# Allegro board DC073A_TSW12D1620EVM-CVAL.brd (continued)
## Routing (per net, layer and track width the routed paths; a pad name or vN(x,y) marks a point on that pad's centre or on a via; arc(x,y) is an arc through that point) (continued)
VBUS: length 10.1
  TOP w0.381: v1(13.92,39.23) 13.97,39.18 C167.1 13.97,38.27 v1(13.9,38.2)
  BOTTOM w0.381: U10.1 12,42.33 11.89,42.44 ; 11.89,42.44 12,42.54 12.58,42.54 13.9,41.22 U10.3 ; 11.89,42.44 R132.1
VBUSS: length 2.3
  TOP w0.381: FB3.1 11.9,35.31 v2(12,35.21)
VDDD33: length 2.7
  TOP w0.305: v1(24.42,32.2) 24.61,32.01 C170.1 24.61,31.4 24.44,31.22 v1(24.44,30.67)
  BOTTOM w0.152: U13.8 24.44,31.22 v1(24.44,30.67)
  vias: v1(5.97,115.82) v1(25.87,46.32) v1(25.93,43.44) v1(26.1,45.77) v1(26.14,42.89) v1(30.78,45.13) v1(30.78,44.12) v1(30.76,42.8) v1(52.25,35.94) v1(53.59,35.94) v1(57.89,35.94) v1(57.89,35.28) v1(57.91,31.39) v1(59.23,35.94) v1(59.23,35.28) v1(59.26,31.39) v2(16.59,59.97) v2(16.94,99.52) v2(16.97,107.52) v2(16.97,98.53) v2(17.45,78.03) v2(17.45,76.89) v2(17.42,75.72) v2(17.53,80.14) v2(17.48,79.1) v2(17.91,107.52) v2(17.88,99.49) v2(17.91,98.5) v2(18.11,59.94) v2(18.14,57.91) v2(18.14,56.39) v2(18.62,79.07) v2(18.59,78) v2(18.59,76.86) v2(18.57,75.69) v2(18.67,80.11) v2(19.74,78) v2(19.74,76.86) v2(19.71,75.69) v2(19.81,80.11) v2(19.76,79.07) v2(19.99,48.46) v2(29.08,34.92) v2(29.08,32.64) v2(29.08,31.5) v2(37.97,47.62) v2(37.97,45.09) v2(53.31,37.59) v2(65.05,117.27) v2(65.07,115.57) v2(65.81,116.41) v2(66.55,117.27) v2(66.52,115.57) v2(67.26,121.74) v2(67.26,110.62) v2(69.09,122.66) v2(69.09,121.72) v2(69.09,110.85) v2(69.09,109.93) v2(70.36,124.79) v2(71.63,124.79) v2(72.9,124.79) v2(74.17,124.79) v2(76.83,119.91) v2(76.81,119) v2(77.85,119.91) v2(77.85,119) v4(16.71,106.65) v4(17.25,106.65) v4(26.2,52.03) v4(26.2,51.22) v4(26.2,50.37) v4(28.7,40.84) v4(28.7,39.97) v4(28.7,39.15) v4(31.7,52.05) v4(31.7,51.22) v4(31.7,50.37) v4(33.24,44.85) v4(34.07,44.84) v4(34.85,44.84)
VDDL19: length 285.6
  L03_PWR w0.762: v2(64.85,38.05) 64.85,38.15
  L05_SIG1 w0.508: JP6.1 76.96,148.31 78.97,146.3 78.97,140.92 76.96,138.91 J12.1 ; JP6.1 JP7.1 JP8.1 JP9.1 ; JP6.1 JP5.1 JP4.1 JP3.1
  L08_SIG2 w0.762: v2(64.82,34.47) 63.88,34.47 54.13,24.71 29.13,24.71 19.86,33.99 19.86,46.99 20.75,47.88 20.75,62.38 20.35,62.79 20.35,71.96 21.72,73.33 21.72,93.67 17.73,97.66 12.67,97.66 10.01,100.33 10.01,111.63 9.27,112.37 9.27,125.4 12.73,128.85 12.73,130.51 15.98,133.76 15.98,134.19 18.59,136.8 18.59,137.82 23.83,143.05 31.29,143.05 32.74,144.5 38.25,144.5 42.01,148.26 63.04,148.26 JP9.1
  L10_SIG3 w0.508: v1(68.07,141.6) v1(72.52,141.6) 74.04,141.6 J12.1 ; JP3.1 92.3,146.84 92.3,140.82 v1(90.17,138.68)
  BOTTOM w0.762: J12.1 74.04,141.6 v1(72.52,141.6)
  vias: v1(52.25,35.28) v1(53.59,35.28) v2(54.61,32.77) v2(64.82,35.71) v2(64.87,36.86) v2(65.91,38.05) v2(65.94,36.86) v2(65.89,35.71) v2(65.89,34.47) v2(67.03,38.05) v2(67.01,35.71) v2(67.01,34.47) v2(67.06,36.86) v2(68.25,38.05) v2(68.22,35.71) v2(68.22,34.47) v2(68.28,36.86)
VEE: length 13.2
  TOP w0.305: JP10.3 81.41,116.59 81.84,116.59 87.27,111.15 R84.1 88.7,112.29 U6.8
VINI+: length 10.8
  TOP w0.178: 71.25,88.52 70.78,88.05 70.59,88.05 arc(70.39,88.09) 70.22,88.21 67.49,90.93 arc(67.33,91.17) 67.27,91.46 67.27,91.96 arc(67.21,92.29) 67.02,92.58 64.75,94.84 C2.2
VINI-: length 11
  TOP w0.178: C14.2 64.49,94.62 66.77,92.33 arc(66.89,92.16) 66.93,91.96 66.93,91.46 arc(67.01,91.04) 67.25,90.69 69.97,87.96 arc(70.26,87.77) 70.59,87.71 70.79,87.71 U4.J1
VINQ+: length 10.8
  TOP w0.178: R27.2 64.77,75.84 67.19,78.26 arc(67.38,78.54) 67.44,78.88 67.44,79.51 arc(67.48,79.72) 67.6,79.89 70.17,82.46 arc(70.34,82.57) 70.54,82.61 70.8,82.61 U4.N1
VINQ-: length 11
  TOP w0.178: U4.M1 70.76,82.96 70.54,82.96 arc(70.21,82.89) 69.92,82.7 67.36,80.13 arc(67.17,79.85) 67.1,79.51 67.1,78.88 arc(67.06,78.67) 66.94,78.5 64.51,76.07 R16.2
1P8V_USB: length 1.6
  BOTTOM w0.305: U12.49 32.2,39 32.6,38.6 v2(32.64,38.58)
  vias: v2(32.69,41.15) v2(33.07,39.67) v2(33.4,37.72) v2(33.43,36.73) v2(33.55,38.58) v4(21.98,47.35) v4(22.63,47.35) v4(24.69,40.78) v4(24.7,39.97) v4(24.69,39.12) v4(32.2,40.5) v4(32.2,39.77) v4(32.2,39.14) v4(33.22,47.35) v4(34.07,47.34) v4(34.89,47.35)
3P3USB: length 3.9
  TOP w0.305: v4(23.64,45.84) 24.53,45.84 FB2.2 24.71,47.32 PP6.1 ; v4(22.82,45.84) 21.98,45.84 v4(21.97,45.85)
3P3V_RX: length 1.7
  TOP w0.279: PP3.1 139.06,53.92 R115.2
3P3VAUX: length 65.9
  TOP w0.152: J30.4 94.36,33.71 95.66,35 101.83,35 102.16,35.33 102.16,38.77 v1(101.46,39.47) ; C155.2 v1(139.06,66.78)
  L10_SIG3 w0.127: v1(101.46,39.47) 101.45,39.48 101.45,41.53 110.64,50.72 113.67,50.72 119.74,56.79 124.64,56.79 126.95,54.48 128.04,54.48 129.08,55.52 129.08,56.2 139.06,66.18 v1(139.06,66.78)
12P0V_RX: length 3
  L10_SIG3 w0.127: v1(140.34,62.97) 139.8,62.43 139.8,60.96 v1(140.34,60.43)
/CS: length 89.8
  L10_SIG3 w0.127: v1(28.45,36.83) 18.67,36.83 13.13,42.37 13.13,65.3 12.29,66.14 12.29,70.69 9.68,73.3 9.68,90.27 16.84,97.43 17.75,97.43 18.75,98.42 18.75,104.42 v1(19.66,105.33)
  BOTTOM w0.152: U20.39 17.7,105.64 18.01,105.94 19.05,105.94 v1(19.66,105.33)
/RST: length 18.6
  BOTTOM w0.152: C238.1 SW2.2 R190.2 6.73,116.08 6.73,114.3 6.1,113.67 6.1,107.31 7.24,106.17 J36.11 7.33,106.14 U20.23
ADC_CLK: length 76.2
  TOP w0.152: PP7.1 v1(49.02,35.31)
  L05_SIG1 w0.076: v1(76.33,94.87) 76.33,94.82 75.72,94.21 75.72,93.37 75.34,92.99 70.74,92.99
  L05_SIG1 w0.127: v1(49.02,35.31) 49.02,36.86 66.42,54.25 66.42,65.65 66.29,65.77 66.29,66.78 66.03,67.05 66.03,67.42 66.29,67.68 66.29,75.16 66.41,75.28 66.41,76.14 66,76.54 66,85.38 66.41,85.79 66.41,89.45 69.95,92.99 70.74,92.99
ADC_SCSB: length 80.4
  TOP w0.152: PP8.1 v1(49.02,31.88)
  L05_SIG1 w0.076: v1(75.06,94.87) 75.06,94.72 74.55,94.21 70.74,94.21
  L05_SIG1 w0.127: v1(49.02,31.88) 49.66,32.51 49.66,34.29 49.17,34.77 48.74,34.77 48.36,35.15 48.36,37.19 65.58,54.41 65.58,65.82 65.19,66.21 65.19,66.58 65.58,66.97 65.58,73.56 65.1,74.04 65.1,77.93 64.58,78.45 64.58,81.32 65.1,81.83 65.1,86.39 65.79,87.08 65.79,90.12 69.88,94.21 70.74,94.21
ADC_SDI: length 78.7
  TOP w0.152: PP4.1 47.88,34.16 v1(49.02,34.16)
  L05_SIG1 w0.076: 70.74,95.45 74.37,95.45 v1(75.06,96.14)
  L05_SIG1 w0.127: 70.74,95.45 70.32,95.45 63.72,88.85 63.72,73.22 62.41,71.91 62.41,52.2 47.75,37.54 47.75,35.03 48.67,34.11 48.97,34.11 v1(49.02,34.16)
ADC_SDO: length 80.5
  TOP w0.152: v1(49.02,33.02) 47.75,33.02 PP5.1
  L05_SIG1 w0.076: v1(73.79,97.41) 73.18,96.8 70.74,96.8
  L05_SIG1 w0.127: v1(49.02,33.02) 46.66,35.38 46.66,38 61.84,53.17 61.84,65.69 61.84,65.69 61.84,76.14 61.91,76.22 61.91,76.59 61.84,76.66 61.84,83.26 61.94,83.36 61.94,83.72 61.84,83.82 61.84,87.81 61.84,87.81 61.84,88.16 70.48,96.8 70.74,96.8
AIN: length 1
  TOP w0.381: R3.1 C1.2
AINI: length 7.2
  TOP w0.381: J2.1 47.24,113.04 R5.1 C1.1
AINQ: length 7.2
  TOP w0.381: J5.1 47.42,57.84 47.44,57.84 C29.1
AIP: length 1
  TOP w0.381: R7.1 C6.2
AQN: length 1
  TOP w0.381: R18.1 48.16,60.17 C16.2
AQP: length 1
  TOP w0.381: C29.2 R25.1
BDBUS0: length 0.7
  TOP w0.254: R134.1 29.2,51.93 v4(29.2,51.22)
BDBUS1: length 3.2
  BOTTOM w0.254: v1(29.84,48.11) 29.7,48.25 U12.27
BDBUS2: length 5.8
  TOP w0.254: v1(30.2,49.62) 28.57,49.62 27.2,48.25 27.2,47.65 R136.1
  BOTTOM w0.254: U12.28 v1(30.2,49.62)
BDBUS3: length 3.2
  BOTTOM w0.254: U12.29 30.7,48.2 v1(30.79,48.11)
CALRUN: length 39.5
  L08_SIG2 w0.127: TP1.1 83.31,105.49 76.94,99.11 76.94,96.75 v1(76.33,96.14)
  BOTTOM w0.178: R40.1 77.01,99.42 77.01,96.82 v1(76.33,96.14)
CALRUN_FMC: length 63.9
  TOP w0.152: v1(135.25,84.56) 135.18,84.63 134.42,84.63 120.73,98.32 97.76,98.32 95.99,100.1 78.71,100.1 v1(78.05,99.44)
CALTRG: length 48.9
  L08_SIG2 w0.127: v1(77.6,93.6) 78.26,94.26 78.26,97.51 84.48,103.73 84.48,126.16 85.99,127.67 85.99,135.65 J9.2
  BOTTOM w0.152: R38.1 J9.2
CDBUS0: length 5.6
  BOTTOM w0.152: U12.38 35.44,46.84 35.76,47.17 35.76,49.23 R138.1
CDBUS1: length 4.8
  BOTTOM w0.152: R143.1 36.27,48.34 36.27,46.94 35.68,46.34 U12.39
CDBUS2: length 4.3
  BOTTOM w0.152: R142.2 R149.1 36.32,45.84 U12.40
CDBUS3: length 4.1
  BOTTOM w0.152: U12.41 36.7,45.34 R141.2 R150.1
CDBUS4: length 3.6
  BOTTOM w0.152: R151.1 35.16,44.34 U12.43
CLK+: length 4
  BOTTOM w0.381: C40.1 66.22,83.1 R53.2 65.5,84.75 T1.3
CLK-: length 4.1
  BOTTOM w0.381: T1.1 63.55,83.1 R53.1 65.52,82.36 65.52,82.29
CLKN: length 8.5
  BOTTOM w0.178: v1(71.25,75.82) 71.65,76.22 71.65,76.47 68.38,79.74 68.38,79.93 66.74,81.57 C42.2
CLKP: length 8.5
  BOTTOM w0.178: v1(72.52,77.09) 72.12,76.69 71.92,76.69 68.72,79.89 68.72,80.08 67.04,81.75 C41.2
CPOUT: length 6.9
  BOTTOM w0.178: U7.22 35.39,130.28 C132.1 38.05,131.47 C131.1 38.07,132.61 R90.1
DCLK_DI+: length 23.3
  TOP w0.178: v1(139.06,82.02) 139.06,81.84 138.79,81.56 134.5,81.56 132.18,83.87 131.4,83.87 128.58,86.68 118.45,86.68 C59.2
DCLK_DI-: length 23.3
  TOP w0.178: v1(139.06,80.75) 139.06,80.9 138.75,81.22 134.35,81.22 132.04,83.53 131.25,83.53 128.44,86.34 118.45,86.34 R194.2
DCLK_DID+: length 58.4
  TOP w0.178: v4(107.95,115.21) 108.16,115 108.72,115 112.2,111.52 112.2,110.73 110.34,108.86 110.34,108.36 110.71,107.98 111.22,107.98 113.08,109.85 113.87,109.85 114.45,109.27 114.45,108.49 112.58,106.62 112.58,106.12 112.96,105.74 113.46,105.74 115.33,107.61 116.12,107.61 116.7,107.03 116.7,106.24 114.83,104.37 114.83,103.87 115.2,103.49 115.71,103.49 117.58,105.36 118.36,105.36 118.94,104.78 118.94,103.99 117.07,102.13 117.07,101.62 117.45,101.25 117.95,101.25 119.82,103.11 120.61,103.11 124.39,99.33 135.08,99.33 135.25,99.51 v1(135.25,99.8)
DCLK_DID-: length 58.4
  TOP w0.178: v4(107.95,114.45) 108.16,114.66 108.58,114.66 111.86,111.38 111.86,110.87 109.99,109.01 109.99,108.22 110.57,107.64 111.36,107.64 113.23,109.51 113.73,109.51 114.11,109.13 114.11,108.63 112.24,106.76 112.24,105.97 112.82,105.4 113.6,105.4 115.47,107.26 115.97,107.26 116.35,106.89 116.35,106.38 114.48,104.51 114.48,103.73 115.06,103.15 115.85,103.15 117.72,105.02 118.22,105.02 118.6,104.64 118.6,104.14 116.73,102.27 116.73,101.48 117.31,100.9 118.1,100.9 119.96,102.77 120.47,102.77 124.25,98.99 135.08,98.99 135.25,98.81 v1(135.25,98.53)
DCLK_DQ+: length 23.3
  TOP w0.178: v1(131.44,75.67) 131.44,75.3 131.37,75.22 130.75,75.22 128.5,77.47 128.5,79.1 130.47,81.06 130.47,82.9 129.27,84.09 118.45,84.09 R197.1
DCLK_DQ-: length 23.4
  TOP w0.178: R196.1 118.45,83.75 129.13,83.75 130.12,82.75 130.12,81.21 128.16,79.24 128.16,77.33 130.61,74.88 131.37,74.88 131.44,74.8 v1(131.44,74.4)
DCLK_DQD+: length 57.3
  TOP w0.178: v4(108.71,117.25) 108.92,117.04 109.45,117.04 114.3,112.19 114.8,112.19 116.57,113.96 117.36,113.96 117.94,113.38 117.94,112.59 116.17,110.83 116.17,110.32 116.55,109.94 117.05,109.94 118.82,111.71 119.6,111.71 120.18,111.13 120.18,110.35 118.41,108.58 118.41,108.08 118.79,107.7 119.29,107.7 121.06,109.47 121.85,109.47 122.43,108.89 122.43,108.1 120.66,106.33 120.66,105.83 121.04,105.45 121.54,105.45 123.31,107.22 124.1,107.22 124.67,106.64 124.67,105.86 123,104.18 123,103.49 124.64,101.85 136.04,101.85 v1(136.53,102.34)
DCLK_DQD-: length 57.3
  TOP w0.178: v4(108.71,116.48) 108.92,116.69 109.31,116.69 114.16,111.85 114.95,111.85 116.71,113.62 117.22,113.62 117.59,113.24 117.59,112.74 115.83,110.97 115.83,110.18 116.4,109.6 117.19,109.6 118.96,111.37 119.46,111.37 119.84,110.99 119.84,110.49 118.07,108.72 118.07,107.94 118.65,107.36 119.44,107.36 121.21,109.12 121.71,109.12 122.09,108.75 122.09,108.24 120.32,106.48 120.32,105.69 120.9,105.11 121.68,105.11 123.45,106.88 123.95,106.88 124.33,106.5 124.33,106 122.66,104.32 122.66,103.35 124.5,101.51 136.11,101.51 136.53,101.09 v1(136.53,101.07)
DCLK_RST+: length 42.2
  L10_SIG3 w0.076: v1(39.5,81.53) 39.5,75.49 39.68,75.3 47.69,75.3 49.17,73.83 53.01,73.83 56.47,77.28 62.22,77.28 63.21,76.29 66.5,76.29 67.31,75.47 71.09,75.47 71.1,75.46 71.39,75.46 71.4,75.47 71.77,75.47 71.91,75.32 72.02,75.32 v1(72.52,75.82)
DCLK_RST-: length 42
  L10_SIG3 w0.076: v1(71.25,74.55) 71.74,75.04 71.74,75.15 71.67,75.23 71.5,75.23 71.49,75.22 71,75.22 70.99,75.23 67.21,75.23 66.4,76.05 63.11,76.05 62.12,77.04 56.57,77.04 53.11,73.58 49.07,73.58 47.59,75.06 39.71,75.06 39.5,74.85 v1(39.5,68.83)
DCLKI+: length 5.9
  L05_SIG1 w0.076: v1(94.11,85.98) 94.55,85.98 94.62,86.06 94.62,86.3 94.96,86.64 96.45,86.64 97.18,87.36 97.56,87.36 98.28,86.64 98.63,86.64 v4(98.88,86.89)
DCLKI-: length 5.9
  L05_SIG1 w0.076: v4(98.88,86.13) 98.62,86.4 98.18,86.4 97.46,87.12 97.28,87.12 96.44,86.29 96.44,86.18 96.36,86.11 96.14,86.11 96.06,86.18 96.06,86.29 95.95,86.4 95.06,86.4 94.86,86.2 94.86,86.06 94.94,85.98 v1(95.38,85.98)
DCLKIN: length 65.6
  TOP w0.178: R194.1 117.42,86.34 104.91,86.34 104.35,86.9 104.35,87.72 104.91,88.27 112.98,88.27 113.25,88.53 113.25,89.27 113,89.52 104.91,89.52 104.35,90.07 104.35,90.89 104.91,91.45 113.55,91.45 113.91,91.8 113.91,92.34 113.48,92.76 103.05,92.76 102.72,92.43 102.72,86.72 102.34,86.34 99.7,86.34 R65.1
DCLKIP: length 65.6
  TOP w0.178: R195.1 117.42,86.68 105.05,86.68 104.7,87.04 104.7,87.57 105.05,87.93 113.12,87.93 113.59,88.39 113.59,89.41 113.14,89.86 105.05,89.86 104.7,90.21 104.7,90.75 105.05,91.1 113.69,91.1 114.25,91.66 114.25,92.48 113.62,93.1 102.91,93.1 102.37,92.57 102.37,86.86 102.2,86.68 99.7,86.68 R64.1
DCLKQ+: length 5.9
  L05_SIG1 w0.076: v4(98.88,84.3) 98.62,84.04 97.52,84.04 96.15,85.41 94.94,85.41 94.62,85.09 94.62,84.79 94.55,84.71 v1(94.11,84.71)
DCLKQ-: length 5.9
  L05_SIG1 w0.076: v4(98.88,83.54) 98.62,83.8 97.42,83.8 96.64,84.58 96.48,84.58 96.42,84.51 96.23,84.51 96.15,84.6 96.15,84.78 96.21,84.85 96.21,85 96.05,85.17 95.04,85.17 94.86,84.99 94.86,84.79 94.94,84.71 v1(95.38,84.71)
DCLKQN: length 65.6
  TOP w0.178: R81.1 99.7,83.75 112.66,83.75 113.01,83.39 113.01,82.86 112.66,82.51 103.55,82.51 103.15,82.1 103.15,80.98 103.55,80.58 111.29,80.58 111.47,80.4 111.47,79.51 111.29,79.33 103.55,79.33 103,78.77 103,77.96 103.55,77.4 113.49,77.4 114.81,78.71 114.81,79.68 115.81,80.68 115.81,82.06 114.94,82.92 114.94,83.39 115.3,83.75 117.42,83.75 R196.2
DCLKQP: length 65.6
  TOP w0.178: R80.1 99.7,84.09 112.8,84.09 113.36,83.54 113.36,82.72 112.8,82.16 103.7,82.16 103.49,81.96 103.49,81.12 103.7,80.92 111.43,80.92 111.81,80.54 111.81,79.37 111.43,78.99 103.7,78.99 103.34,78.63 103.34,78.1 103.7,77.74 113.35,77.74 114.47,78.86 114.47,79.82 115.47,80.83 115.47,81.91 114.6,82.78 114.6,83.54 115.16,84.09 117.42,84.09 R197.2
DDRPH: length 85.6
  L08_SIG2 w0.127: v1(75.06,74.55) 74.4,75.21 71.09,75.21 68.5,77.8 68.5,81.28 69.09,81.86 69.09,90.25 68.52,90.82 68.52,91.19 69.02,91.7 69.02,102.22 75.15,108.34 75.15,118.99 72.36,121.77 72.36,125.45 71.02,126.8 68.88,126.8 67.69,127.99 67.69,132.89 65.3,135.28 65.3,144.63 JP9.2
DES: length 77.5
  L10_SIG3 w0.127: v1(76.33,75.82) 75.79,75.29 74.88,75.29 74.6,75.56 74.6,96.44 74.24,96.8 74.24,98.84 74.26,98.85 74.26,99.22 74.24,99.23 74.24,108.79 77.37,111.91 77.37,130.51 78.82,131.95 78.82,140 JP7.2
DEVCLKIN: length 24.3
  BOTTOM w0.381: v1(39.5,95.5) 48.06,95.5 56.62,86.94 59.71,86.94 T1.6
DI0+: length 81.3
  L05_SIG1 w0.076: v1(92.84,96.14) 92.34,95.64 92.34,95.53 92.42,95.46 92.58,95.46 92.59,95.47 93.05,95.47 93.37,95.78 93.37,96.49 93.83,96.95 94.2,96.95 94.64,97.39 94.64,97.69 95,98.04 100.16,98.04 107.55,90.65 107.78,90.65 107.99,90.86 108.16,90.86 108.37,90.65 108.76,90.65 109.16,91.05 109.16,91.76 109.45,92.05 110.19,92.05 110.48,91.76 110.48,89.41 110.63,89.26 111.17,89.26 111.32,89.41 111.32,91.76 111.61,92.05 112.35,92.05 112.64,91.76 112.64,89.41 112.79,89.26 113.33,89.26 113.48,89.41 113.48,91.76 113.77,92.05 114.51,92.05 114.8,91.76 114.8,89.41 114.95,89.26 115.48,89.26 115.64,89.41 115.64,91.76 115.93,92.05 116.66,92.05 116.96,91.76 116.96,89.41 117.11,89.26 117.54,89.26 117.8,89.51 117.8,91.76 118.09,92.05 118.52,92.05 119.91,90.65 120.7,90.65 129.86,81.5 135.61,81.5 136.04,81.06 136.04,80.64 136.52,80.16 138.13,80.16 138.65,79.65 138.65,79.3 138.99,78.96 140.26,78.96 140.34,79.04 v1(140.34,79.48)
DI0-: length 81.3
  L05_SIG1 w0.076: v1(91.57,94.87) 92.06,95.36 92.17,95.36 92.32,95.22 92.68,95.22 92.69,95.22 93.15,95.22 93.61,95.68 93.61,96.39 93.93,96.71 94.3,96.71 94.88,97.29 94.88,97.59 95.1,97.8 100.06,97.8 107.45,90.41 108.86,90.41 109.4,90.95 109.4,91.66 109.55,91.81 110.09,91.81 110.24,91.66 110.24,89.31 110.53,89.01 111.27,89.01 111.56,89.31 111.56,91.66 111.71,91.81 112.25,91.81 112.4,91.66 112.4,89.31 112.69,89.01 113.43,89.01 113.72,89.31 113.72,91.66 113.87,91.81 114.41,91.81 114.56,91.66 114.56,89.31 114.85,89.01 115.58,89.01 115.88,89.31 115.88,91.66 116.03,91.81 116.56,91.81 116.72,91.66 116.72,89.31 117.01,89.01 117.64,89.01 118.04,89.41 118.04,91.66 118.19,91.81 118.42,91.81 119.81,90.41 120.6,90.41 129.76,81.25 135.51,81.25 135.8,80.96 135.8,80.54 136.42,79.92 138.03,79.92 138.4,79.55 138.4,79.2 138.89,78.72 140.26,78.72 140.34,78.64 v1(140.34,78.21)
DI1+: length 81.2
  L05_SIG1 w0.076: v1(94.11,96.14) 94.51,96.14 94.61,96.25 94.61,96.47 95.08,96.94 99.23,96.94 106.78,89.38 106.78,81.2 106.32,80.75 106.32,80.29 106.6,80.01 107.88,80.01 108.08,80.21 108.08,84.18 108.41,84.51 109.11,84.51 109.4,84.21 109.4,80.21 109.55,80.06 110.09,80.06 110.24,80.21 110.24,84.21 110.53,84.51 111.26,84.51 111.56,84.21 111.56,80.21 111.71,80.06 112.21,80.06 112.36,80.21 112.36,84.17 112.69,84.51 113.42,84.51 113.72,84.21 113.72,80.22 113.88,80.06 114.22,80.06 116.47,82.31 126.64,82.31 128.89,80.06 132.64,80.06 133.74,78.96 133.91,78.96 133.99,79.04 v1(133.99,79.48)
DI1-: length 81.3
  L05_SIG1 w0.076: v1(95.38,96.14) 94.98,96.14 94.85,96.26 94.85,96.37 95.18,96.7 96.03,96.7 96.23,96.49 96.41,96.49 96.61,96.7 99.13,96.7 99.43,96.39 99.43,96.17 99.59,96.01 99.81,96.01 106.54,89.28 106.54,88.89 106.32,88.68 106.32,88.51 106.54,88.3 106.54,81.3 106.08,80.85 106.08,80.19 106.5,79.77 107.98,79.77 108.32,80.11 108.32,84.08 108.51,84.26 109.01,84.26 109.16,84.11 109.16,80.11 109.45,79.82 110.19,79.82 110.48,80.11 110.48,84.11 110.63,84.26 111.16,84.26 111.32,84.11 111.32,80.11 111.61,79.82 112.31,79.82 112.6,80.11 112.6,84.07 112.79,84.26 113.32,84.26 113.48,84.11 113.48,80.12 113.78,79.82 114.32,79.82 116.57,82.07 126.54,82.07 128.79,79.82 132.54,79.82 133.64,78.72 133.91,78.72 133.99,78.64 v1(133.99,78.21)
DI2+: length 81.4
  L05_SIG1 w0.076: v1(94.11,94.87) 94.51,94.87 94.61,94.97 94.61,95.22 94.95,95.57 98.88,95.57 105.44,89.01 105.44,81 104.19,79.76 104.19,79.15 104.53,78.8 125.49,78.8 125.59,78.91 125.59,79.44 125.38,79.65 116.94,79.65 116.71,79.88 116.71,80.62 117.01,80.91 126.23,80.91 126.91,80.22 126.91,78.37 127.33,77.95 128.49,77.95 129.53,78.99 132.52,78.99 133.75,77.76 134.3,77.76 134.57,78.03 134.57,80.01 134.79,80.23 135.18,80.23 135.25,80.31 v1(135.25,80.75)
DI2-: length 81.4
  L05_SIG1 w0.076: v1(95.38,94.87) 94.98,94.87 94.88,94.97 94.88,95.11 95.09,95.33 95.9,95.33 96.1,95.12 96.28,95.12 96.48,95.33 98.78,95.33 99.03,95.07 99.03,94.77 99.15,94.65 99.46,94.65 105.19,88.91 105.19,88.61 105.03,88.44 105.03,88.23 105.19,88.06 105.19,81.1 103.95,79.86 103.95,79.05 104.43,78.56 125.59,78.56 125.83,78.81 125.83,79.54 125.48,79.9 117.04,79.9 116.95,79.98 116.95,80.52 117.11,80.67 126.13,80.67 126.67,80.12 126.67,78.27 127.23,77.71 128.59,77.71 129.63,78.75 132.42,78.75 133.65,77.52 134.4,77.52 134.81,77.93 134.81,79.91 134.89,79.99 135.18,79.99 135.25,79.91 v1(135.25,79.48)
DI3+: length 81.3
  L05_SIG1 w0.076: v1(92.84,93.6) 92.84,93.24 93.03,93.05 97.97,93.05 102.55,88.47 102.55,81.51 101.52,80.48 101.52,78.38 99.59,76.45 99.59,74.9 100.18,74.32 101.74,74.32 101.89,74.47 101.89,75.02 102.19,75.31 102.92,75.31 103.21,75.02 103.21,74.47 103.37,74.32 103.9,74.32 104.05,74.47 104.05,75.02 104.35,75.31 105.08,75.31 105.37,75.02 105.37,74.47 105.53,74.32 106.06,74.32 106.21,74.47 106.21,75.02 106.5,75.31 107.24,75.31 107.53,75.02 107.53,74.47 107.68,74.32 108.22,74.32 108.37,74.47 108.37,75.02 108.66,75.31 109.4,75.31 109.69,75.02 109.69,74.47 109.84,74.32 110.38,74.32 110.53,74.47 110.53,75.02 110.82,75.31 111.56,75.31 111.85,75.02 111.85,74.47 112,74.32 112.54,74.32 112.69,74.47 112.69,75.02 112.98,75.31 113.72,75.31 114.01,75.02 114.01,74.47 114.16,74.32 114.69,74.32 114.85,74.47 114.85,75.02 115.14,75.31 115.87,75.31 116.17,75.02 116.17,74.47 116.32,74.32 116.85,74.32 117.01,74.47 117.01,75.02 117.3,75.31 118.03,75.31 118.33,75.02 118.33,74.47 118.48,74.32 119.01,74.32 119.17,74.47 119.17,75.02 119.46,75.31 120.19,75.31 120.49,75.02 120.49,74.47 120.64,74.32 121.17,74.32 121.32,74.47 121.32,75.02 121.62,75.31 122.35,75.31 122.65,75.02 122.65,74.47 122.8,74.32 123.33,74.32 123.48,74.47 123.48,75.02 123.78,75.31 124.51,75.31 124.8,75.02 124.8,74.47 124.96,74.32 125.49,74.32 125.64,74.47 125.64,75.02 125.94,75.31 126.67,75.31 126.96,75.02 126.96,74.47 127.34,74.09 128.14,74.09 130.47,76.42 132.9,76.42 133.44,75.88 133.44,75.49 133.77,75.15 133.91,75.15 133.99,75.23 v1(133.99,75.67)
DI3-: length 81.2
  L05_SIG1 w0.076: v1(92.84,92.33) 92.84,92.62 93.03,92.81 97.87,92.81 102.31,88.37 102.31,81.61 101.28,80.58 101.28,78.48 99.35,76.55 99.35,74.8 100.08,74.08 101.84,74.08 102.13,74.37 102.13,74.92 102.29,75.07 102.82,75.07 102.97,74.92 102.97,74.37 103.27,74.08 104,74.08 104.29,74.37 104.29,74.92 104.45,75.07 104.98,75.07 105.13,74.92 105.13,74.37 105.43,74.08 106.16,74.08 106.45,74.37 106.45,74.92 106.61,75.07 107.14,75.07 107.29,74.92 107.29,74.37 107.58,74.08 108.32,74.08 108.61,74.37 108.61,74.92 108.76,75.07 109.3,75.07 109.45,74.92 109.45,74.37 109.74,74.08 110.48,74.08 110.77,74.37 110.77,74.92 110.92,75.07 111.46,75.07 111.61,74.92 111.61,74.37 111.9,74.08 112.64,74.08 112.93,74.37 112.93,74.92 113.08,75.07 113.62,75.07 113.77,74.92 113.77,74.37 114.06,74.08 114.8,74.08 115.09,74.37 115.09,74.92 115.24,75.07 115.77,75.07 115.93,74.92 115.93,74.37 116.22,74.08 116.95,74.08 117.25,74.37 117.25,74.92 117.4,75.07 117.93,75.07 118.09,74.92 118.09,74.37 118.38,74.08 119.11,74.08 119.41,74.37 119.41,74.92 119.56,75.07 120.09,75.07 120.24,74.92 120.24,74.37 120.54,74.08 121.27,74.08 121.57,74.37 121.57,74.92 121.72,75.07 122.25,75.07 122.4,74.92 122.4,74.37 122.7,74.08 123.43,74.08 123.72,74.37 123.72,74.92 123.88,75.07 124.41,75.07 124.56,74.92 124.56,74.37 124.86,74.08 125.59,74.08 125.88,74.37 125.88,74.92 126.04,75.07 126.57,75.07 126.72,74.92 126.72,74.37 127.24,73.85 128.24,73.85 130.57,76.17 132.8,76.17 133.2,75.78 133.2,75.39 133.67,74.91 133.91,74.91 133.99,74.83 v1(133.99,74.4)
DI4+: length 81.3
  L05_SIG1 w0.076: v1(94.11,93.6) 94.51,93.6 94.61,93.7 94.61,94 94.93,94.32 98.4,94.32 103.99,88.73 103.99,81.05 102.57,79.63 102.57,77.85 101.42,76.71 101.42,76.45 101.57,76.3 103.86,76.3 104.01,76.45 104.01,77.15 104.38,77.52 104.96,77.52 105.33,77.15 105.33,76.45 105.48,76.3 106.01,76.3 106.17,76.45 106.17,77.15 106.46,77.44 107.19,77.44 107.49,77.15 107.49,76.45 107.64,76.3 108.17,76.3 108.33,76.45 108.33,77.15 108.62,77.44 109.35,77.44 109.65,77.15 109.65,76.45 109.8,76.3 110.33,76.3 110.49,76.45 110.49,77.15 110.78,77.44 111.51,77.44 111.81,77.15 111.81,76.45 111.96,76.3 112.49,76.3 112.64,76.45 112.64,77.15 112.94,77.44 113.67,77.44 113.96,77.15 113.96,76.45 114.12,76.3 114.65,76.3 114.8,76.45 114.8,77.15 115.1,77.44 115.83,77.44 116.12,77.15 116.12,76.45 116.28,76.3 116.81,76.3 117.01,76.5 117.01,77.19 117.26,77.44 117.99,77.44 118.33,77.11 118.33,76.41 118.44,76.3 118.97,76.3 119.12,76.45 119.12,77.15 119.41,77.44 120.15,77.44 120.44,77.15 120.44,76.45 120.59,76.3 121.13,76.3 121.28,76.45 121.28,77.15 121.57,77.44 122.31,77.44 122.6,77.15 122.6,76.45 122.75,76.3 123.29,76.3 123.44,76.45 123.44,77.15 123.73,77.44 124.47,77.44 124.76,77.15 124.76,76.45 124.91,76.3 125.45,76.3 125.6,76.45 125.6,77.15 125.89,77.44 126.63,77.44 126.92,77.15 126.92,76.45 127.4,75.97 128.26,75.97 129.92,77.64 132.95,77.64 133.38,77.21 133.38,76.9 133.84,76.43 135.18,76.43 135.25,76.5 v1(135.25,76.94)
DI4-: length 81.3
  L05_SIG1 w0.076: v1(135.25,75.67) 135.25,76.11 135.18,76.19 133.74,76.19 133.13,76.8 133.13,77.11 132.85,77.39 130.02,77.39 128.36,75.73 127.3,75.73 126.68,76.35 126.68,77.05 126.53,77.2 125.99,77.2 125.84,77.05 125.84,76.35 125.55,76.06 124.81,76.06 124.52,76.35 124.52,77.05 124.37,77.2 123.83,77.2 123.68,77.05 123.68,76.35 123.39,76.06 122.65,76.06 122.36,76.35 122.36,77.05 122.21,77.2 121.67,77.2 121.52,77.05 121.52,76.35 121.23,76.06 120.49,76.06 120.2,76.35 120.2,77.05 120.05,77.2 119.51,77.2 119.36,77.05 119.36,76.35 119.07,76.06 118.34,76.06 118.08,76.31 118.08,77.01 117.89,77.2 117.36,77.2 117.25,77.09 117.25,76.4 116.91,76.06 116.18,76.06 115.88,76.35 115.88,77.05 115.73,77.2 115.2,77.2 115.04,77.05 115.04,76.35 114.75,76.06 114.02,76.06 113.72,76.35 113.72,77.05 113.57,77.2 113.04,77.2 112.89,77.05 112.89,76.35 112.59,76.06 111.86,76.06 111.56,76.35 111.56,77.05 111.41,77.2 110.88,77.2 110.73,77.05 110.73,76.35 110.43,76.06 109.7,76.06 109.41,76.35 109.41,77.05 109.25,77.2 108.72,77.2 108.57,77.05 108.57,76.35 108.27,76.06 107.54,76.06 107.25,76.35 107.25,77.05 107.09,77.2 106.56,77.2 106.41,77.05 106.41,76.35 106.11,76.06 105.38,76.06 105.09,76.35 105.09,77.05 104.86,77.28 104.48,77.28 104.25,77.05 104.25,76.35 103.96,76.06 101.47,76.06 101.18,76.35 101.18,76.81 102.32,77.95 102.32,79.73 103.75,81.15 103.75,87.64 103.61,87.78 103.61,88.09 103.75,88.23 103.75,88.63 98.94,93.44 98.68,93.44 98.54,93.58 98.54,93.84 98.3,94.08 96.57,94.08 96.39,93.9 96.19,93.9 96.01,94.08 95.07,94.08 94.88,93.89 94.88,93.7 94.98,93.6 v1(95.38,93.6)
DI5+: length 81.1
  L08_SIG2 w0.076: v1(94.11,92.33) 94.51,92.33 94.61,92.23 94.61,92.03 95.21,91.43 96.23,91.43 99.35,88.3 99.35,84.41 99.98,83.78 100.28,83.78 101.05,83.78 101.34,84.08 101.34,85.43 101.5,85.59 102.03,85.59 102.18,85.43 102.18,84.08 102.48,83.78 103.21,83.78 103.5,84.08 103.5,85.43 103.65,85.59 104.19,85.59 104.34,85.43 104.34,84.08 104.63,83.78 105.37,83.78 105.66,84.08 105.66,85.43 105.81,85.59 106.35,85.59 106.5,85.43 106.5,84.08 106.79,83.78 107.53,83.78 107.82,84.08 107.82,85.43 107.97,85.59 108.51,85.59 108.66,85.43 108.66,84.08 108.95,83.78 109.69,83.78 109.98,84.08 109.98,85.46 110.11,85.59 110.67,85.59 110.82,85.43 110.82,84.08 111.11,83.78 111.84,83.78 112.14,84.08 112.14,85.43 112.29,85.59 112.7,85.59 112.98,85.31 112.98,84.08 113.27,83.78 113.97,83.78 114.31,84.13 114.31,85.51 114.39,85.59 114.98,85.59 115.14,85.43 115.14,84.08 115.43,83.78 138.28,83.78 140.04,82.02 140.04,81.76 140.24,81.55 140.51,81.55 140.89,81.17 140.89,79.12 140.77,78.99 140.77,78.61 140.89,78.49 140.89,78.01 140.58,77.7 139.24,77.7 139.06,77.88 v1(139.06,78.21)
DI5-: length 81.3
  L08_SIG2 w0.076: v1(139.06,76.94) 139.06,77.28 139.24,77.46 140.68,77.46 141.14,77.91 141.14,81.27 138.38,84.02 115.53,84.02 115.38,84.18 115.38,85.53 115.08,85.83 114.29,85.83 114.07,85.61 114.07,84.23 113.87,84.02 113.37,84.02 113.22,84.18 113.22,85.41 112.8,85.83 112.19,85.83 111.9,85.53 111.9,84.18 111.74,84.02 111.21,84.02 111.06,84.18 111.06,85.53 110.77,85.83 110.01,85.83 109.74,85.56 109.74,84.18 109.59,84.02 109.05,84.02 108.9,84.18 108.9,85.53 108.61,85.83 107.87,85.83 107.58,85.53 107.58,84.18 107.43,84.02 106.89,84.02 106.74,84.18 106.74,85.53 106.45,85.83 105.71,85.83 105.42,85.53 105.42,84.18 105.27,84.02 104.73,84.02 104.58,84.18 104.58,85.53 104.29,85.83 103.55,85.83 103.26,85.53 103.26,84.18 103.11,84.02 102.58,84.02 102.42,84.18 102.42,85.53 102.13,85.83 101.4,85.83 101.1,85.53 101.1,84.18 100.95,84.02 100.18,84.02 100.18,84.02 100.08,84.02 99.59,84.51 99.59,88.4 96.33,91.67 95.31,91.67 94.88,92.11 94.88,92.23 94.98,92.33 v1(95.38,92.33)
DI6+: length 81.3
  L08_SIG2 w0.076: v1(92.84,91.06) 93.28,91.06 93.35,91.14 93.35,91.39 93.73,91.77 94.36,91.77 94.82,91.31 94.82,91.02 95.27,90.56 95.68,90.56 96.56,89.69 96.56,88.44 95.81,87.69 93.9,87.69 93.6,87.39 93.6,73.01 94.54,72.07 97.49,72.07 98.92,73.51 99.62,73.51 99.91,73.21 99.91,72.85 100.07,72.69 100.6,72.69 100.75,72.85 100.75,73.21 101.05,73.51 101.78,73.51 102.07,73.21 102.07,72.85 102.23,72.69 102.76,72.69 102.91,72.85 102.91,73.21 103.2,73.51 103.94,73.51 104.23,73.21 104.23,72.85 104.38,72.69 104.92,72.69 105.07,72.85 105.07,73.21 105.36,73.51 106.1,73.51 106.39,73.21 106.39,72.85 106.54,72.69 107.08,72.69 107.23,72.85 107.23,73.21 107.52,73.51 108.26,73.51 108.55,73.21 108.55,72.85 108.7,72.69 109.24,72.69 109.39,72.85 109.39,73.21 109.68,73.51 110.42,73.51 110.71,73.21 110.71,72.85 110.86,72.69 111.39,72.69 111.55,72.85 111.55,73.21 111.84,73.51 112.57,73.51 112.87,73.21 112.87,72.85 113.02,72.69 113.55,72.69 113.71,72.85 113.71,73.21 114,73.51 114.73,73.51 115.03,73.21 115.03,72.85 115.18,72.69 115.71,72.69 115.86,72.85 115.86,73.21 116.16,73.51 116.89,73.51 117.19,73.21 117.19,72.85 117.34,72.69 117.87,72.69 118.02,72.85 118.02,73.21 118.32,73.51 119.05,73.51 119.34,73.21 119.34,72.85 119.5,72.69 120.03,72.69 120.18,72.85 120.18,73.21 120.48,73.51 121.21,73.51 121.5,73.21 121.5,72.85 121.66,72.69 122.19,72.69 122.34,72.85 122.34,73.21 122.64,73.51 123.37,73.51 123.66,73.21 123.66,72.85 123.82,72.69 124.35,72.69 124.5,72.85 124.5,73.21 124.79,73.51 125.53,73.51 125.82,73.21 125.82,72.85 125.97,72.69 126.51,72.69 126.66,72.85 126.66,73.21 126.95,73.51 127.69,73.51 128.5,72.69 129.78,72.69 131.14,71.34 133.87,71.34 133.89,71.32 133.99,71.42 v1(133.99,71.86)
DI6-: length 81.2
  L08_SIG2 w0.076: v1(94.11,91.06) 93.67,91.06 93.59,91.14 93.59,91.29 93.83,91.53 94.26,91.53 94.58,91.21 94.58,90.92 94.74,90.76 94.74,90.6 94.68,90.54 94.68,90.38 94.79,90.27 94.95,90.27 95.01,90.33 95.17,90.33 95.17,90.32 95.58,90.32 96.32,89.59 96.32,88.54 95.71,87.93 93.8,87.93 93.36,87.49 93.36,72.91 94.44,71.83 97.59,71.83 99.02,73.27 99.52,73.27 99.67,73.11 99.67,72.75 99.97,72.45 100.7,72.45 100.99,72.75 100.99,73.11 101.15,73.27 101.68,73.27 101.83,73.11 101.83,72.75 102.13,72.45 102.86,72.45 103.15,72.75 103.15,73.11 103.3,73.27 103.84,73.27 103.99,73.11 103.99,72.75 104.28,72.45 105.02,72.45 105.31,72.75 105.31,73.11 105.46,73.27 106,73.27 106.15,73.11 106.15,72.75 106.44,72.45 107.18,72.45 107.47,72.75 107.47,73.11 107.62,73.27 108.16,73.27 108.31,73.11 108.31,72.75 108.6,72.45 109.34,72.45 109.63,72.75 109.63,73.11 109.78,73.27 110.31,73.27 110.47,73.11 110.47,72.75 110.76,72.45 111.49,72.45 111.79,72.75 111.79,73.11 111.94,73.27 112.47,73.27 112.63,73.11 112.63,72.75 112.92,72.45 113.65,72.45 113.95,72.75 113.95,73.11 114.1,73.27 114.63,73.27 114.79,73.11 114.79,72.75 115.08,72.45 115.81,72.45 116.11,72.75 116.11,73.11 116.26,73.27 116.79,73.27 116.94,73.11 116.94,72.75 117.24,72.45 117.97,72.45 118.27,72.75 118.27,73.11 118.42,73.27 118.95,73.27 119.1,73.11 119.1,72.75 119.4,72.45 120.13,72.45 120.42,72.75 120.42,73.11 120.58,73.27 121.11,73.27 121.26,73.11 121.26,72.75 121.56,72.45 122.29,72.45 122.58,72.75 122.58,73.11 122.74,73.27 123.27,73.27 123.42,73.11 123.42,72.75 123.72,72.45 124.45,72.45 124.74,72.75 124.74,73.11 124.89,73.27 125.43,73.27 125.58,73.11 125.58,72.75 125.87,72.45 126.61,72.45 126.9,72.75 126.9,73.11 127.05,73.27 127.59,73.27 128.4,72.45 129.68,72.45 131.04,71.09 133.77,71.09 133.99,70.88 v1(133.99,70.59)
DI7+: length 81.3
  L05_SIG1 w0.076: v1(91.57,89.79) 92.01,89.79 92.08,89.87 92.08,90.35 92.3,90.56 98.6,90.56 101.21,87.96 101.21,82.13 100.28,81.2 100.28,78.69 98.55,76.96 98.55,72.63 98.94,72.24 99.59,72.24 99.97,72.61 99.97,73.16 100.26,73.46 101,73.46 101.29,73.16 101.29,72.82 101.44,72.67 101.98,72.67 102.13,72.82 102.13,73.16 102.42,73.46 103.16,73.46 103.45,73.16 103.45,72.82 103.6,72.67 104.14,72.67 104.29,72.82 104.29,73.16 104.58,73.46 105.32,73.46 105.61,73.16 105.61,72.82 105.76,72.67 106.29,72.67 106.45,72.82 106.45,73.16 106.74,73.46 107.47,73.46 107.77,73.16 107.77,72.82 107.92,72.67 108.45,72.67 108.61,72.82 108.61,73.16 108.9,73.46 109.63,73.46 109.93,73.16 109.93,72.76 110,72.68 110.63,72.68 110.77,72.82 110.77,73.16 111.06,73.46 111.79,73.46 112.09,73.16 112.09,72.82 112.24,72.67 112.77,72.67 112.92,72.82 112.92,73.16 113.22,73.46 113.95,73.46 114.25,73.16 114.25,72.82 114.4,72.67 114.93,72.67 115.08,72.82 115.08,73.16 115.38,73.46 116.11,73.46 116.4,73.16 116.4,72.82 116.56,72.67 117.09,72.67 117.24,72.82 117.24,73.16 117.54,73.46 118.27,73.46 118.56,73.16 118.56,72.82 118.72,72.67 119.25,72.67 119.4,72.82 119.4,73.16 119.69,73.46 120.43,73.46 120.72,73.16 120.72,72.82 120.87,72.67 121.41,72.67 121.56,72.82 121.56,73.16 121.85,73.46 122.59,73.46 122.88,73.16 122.88,72.82 123.03,72.67 123.57,72.67 123.72,72.82 123.72,73.16 124.01,73.46 124.75,73.46 125.04,73.16 125.04,72.82 125.95,71.91 127.46,71.91 130.75,75.2 132.85,75.2 133.38,74.67 133.38,74.41 133.91,73.88 134.36,73.88 134.81,73.43 134.81,72.82 135.02,72.61 135.18,72.61 135.25,72.69 v1(135.25,73.13)
DI7-: length 81.3
  L05_SIG1 w0.076: v1(135.25,71.86) 135.25,72.29 135.18,72.37 134.92,72.37 134.57,72.72 134.57,73.33 134.26,73.63 133.81,73.63 133.13,74.31 133.13,74.57 132.75,74.96 130.85,74.96 127.56,71.67 125.85,71.67 124.8,72.72 124.8,73.06 124.65,73.22 124.11,73.22 123.96,73.06 123.96,72.72 123.67,72.43 122.93,72.43 122.64,72.72 122.64,73.06 122.49,73.22 121.95,73.22 121.8,73.06 121.8,72.72 121.51,72.43 120.77,72.43 120.48,72.72 120.48,73.06 120.33,73.22 119.8,73.22 119.64,73.06 119.64,72.72 119.35,72.43 118.62,72.43 118.32,72.72 118.32,73.06 118.17,73.22 117.64,73.22 117.48,73.06 117.48,72.72 117.19,72.43 116.46,72.43 116.16,72.72 116.16,73.06 116.01,73.22 115.48,73.22 115.32,73.06 115.32,72.72 115.03,72.43 114.3,72.43 114,72.72 114,73.06 113.85,73.22 113.32,73.22 113.17,73.06 113.17,72.72 112.87,72.43 112.14,72.43 111.84,72.72 111.84,73.06 111.69,73.22 111.16,73.22 111.01,73.06 111.01,72.72 110.73,72.44 109.9,72.44 109.69,72.66 109.69,73.06 109.53,73.22 109,73.22 108.85,73.06 108.85,72.72 108.55,72.43 107.82,72.43 107.53,72.72 107.53,73.06 107.37,73.22 106.84,73.22 106.69,73.06 106.69,72.72 106.4,72.43 105.66,72.43 105.37,72.72 105.37,73.06 105.22,73.22 104.68,73.22 104.53,73.06 104.53,72.72 104.24,72.43 103.5,72.43 103.21,72.72 103.21,73.06 103.06,73.22 102.52,73.22 102.37,73.06 102.37,72.72 102.08,72.43 101.34,72.43 101.05,72.72 101.05,73.06 100.9,73.22 100.36,73.22 100.21,73.06 100.21,72.51 99.69,72 98.84,72 98.31,72.53 98.31,77.06 100.04,78.79 100.04,81.3 100.97,82.23 100.97,86.98 100.81,87.14 100.81,87.36 100.97,87.52 100.97,87.86 99.19,89.63 98.96,89.63 98.81,89.79 98.81,90.01 98.5,90.32 96.64,90.32 96.47,90.14 96.26,90.14 96.08,90.32 92.4,90.32 92.32,90.25 92.32,89.87 92.4,89.79 v1(92.84,89.79)
DI8+: length 81.2
  L08_SIG2 w0.076: v1(139.06,74.4) 139.06,74.02 139.14,73.94 139.48,73.94 139.56,74.02 139.56,74.73 139.96,75.12 140.53,75.12 141.62,76.22 141.62,76.33 141.55,76.4 141.55,76.5 141.72,76.67 141.82,76.67 141.89,76.6 142,76.6 142.16,76.76 142.16,80.81 142.09,80.88 142.06,80.88 141.94,81.01 141.94,81.19 142.01,81.26 142.09,81.26 142.16,81.34 142.16,81.57 139.23,84.51 139.12,84.51 139.07,84.45 138.96,84.45 138.8,84.62 138.8,84.72 138.85,84.78 138.85,84.88 138.67,85.06 126.7,85.06 126.41,85.36 126.41,86.6 126.25,86.75 125.72,86.75 125.57,86.6 125.57,85.36 125.28,85.06 124.54,85.06 124.24,85.36 124.24,86.61 124.1,86.75 123.56,86.75 123.47,86.66 123.47,85.42 123.12,85.06 122.38,85.06 122.09,85.36 122.09,86.6 121.94,86.75 121.4,86.75 121.25,86.6 121.25,85.36 120.96,85.06 119.83,85.06 118.29,86.6 103.18,86.6 97.57,92.21 97.46,92.21 97.43,92.18 97.33,92.18 97.16,92.35 97.16,92.45 97.19,92.48 97.19,92.59 96.95,92.82 93.75,92.82 93.67,92.75 93.67,92.63 93.59,92.56 93.37,92.56 93.29,92.63 93.29,92.75 93.21,92.82 92.77,92.82 92.43,92.48 92.43,90.72 92.51,90.64 92.66,90.64 92.74,90.57 92.74,90.34 92.66,90.26 92.51,90.26 92.43,90.18 92.43,89.51 92.68,89.26 93.1,89.26 93.17,89.33 93.17,89.38 93.25,89.46 93.48,89.46 93.55,89.38 93.55,89.33 93.63,89.26 94.44,89.26 94.61,89.43 94.61,89.69 94.51,89.79 v1(94.11,89.79)
DI8-: length 81.3
  L08_SIG2 w0.076: v1(139.06,73.13) 139.06,73.58 139.18,73.7 139.58,73.7 139.8,73.92 139.8,74.63 140.06,74.88 140.63,74.88 142.41,76.66 142.41,81.67 138.77,85.31 126.8,85.31 126.65,85.46 126.65,86.7 126.35,87 125.62,87 125.33,86.7 125.33,85.46 125.18,85.31 124.64,85.31 124.49,85.46 124.49,86.71 124.2,87 123.46,87 123.23,86.76 123.23,85.52 123.02,85.31 122.48,85.31 122.33,85.46 122.33,86.7 122.04,87 121.3,87 121.01,86.7 121.01,85.46 120.86,85.31 119.93,85.31 118.39,86.84 103.28,86.84 97.05,93.07 92.67,93.07 92.19,92.58 92.19,89.41 92.58,89.01 94.57,89.01 94.88,89.32 94.88,89.69 94.98,89.79 v1(95.38,89.79)
DI9+: length 81.2
  L08_SIG2 w0.076: v1(140.34,74.4) 140.34,73.96 140.41,73.88 140.76,73.88 141.16,73.48 141.16,70.36 140.52,69.72 140.51,69.74 140.16,69.74 139.92,69.49 139.92,69.14 139.93,69.13 139.27,68.47 138.89,68.47 138.65,68.22 138.65,67.84 137.98,67.18 137.97,67.2 137.62,67.2 137.38,66.95 137.38,66.6 137.39,66.59 136.73,65.93 94.12,65.93 88.25,71.79 88.25,78.65 90.18,80.58 90.18,85.67 91.29,86.78 91.66,86.78 92.01,87.13 92.01,88.24 91.73,88.52 v1(91.57,88.52)
DI9-: length 81.3
  L08_SIG2 w0.076: v1(92.84,88.52) 92.56,88.52 92.28,88.24 92.28,87.02 91.8,86.54 91.39,86.54 90.42,85.57 90.42,80.48 88.49,78.55 88.49,78.03 88.7,77.83 88.7,77.62 88.49,77.42 88.49,71.89 88.83,71.55 89.18,71.55 89.32,71.41 89.32,71.06 94.22,66.17 94.41,66.17 94.56,66.32 94.74,66.32 94.89,66.17 135.61,66.17 135.84,66.4 136.04,66.4 136.27,66.17 136.63,66.17 137.13,66.67 137.13,67.05 137.52,67.44 137.9,67.44 138.4,67.94 138.4,68.32 138.79,68.71 139.17,68.71 139.67,69.22 139.67,69.59 140.06,69.98 140.44,69.98 140.92,70.46 140.92,70.92 140.61,71.22 140.61,71.37 140.92,71.68 140.92,72.11 140.67,72.36 140.67,72.67 140.92,72.92 140.92,73.38 140.66,73.64 140.41,73.64 140.34,73.56 v1(140.34,73.13)
DI10+: length 81.3
  L05_SIG1 w0.076: v1(94.11,88.52) 94.55,88.52 94.62,88.44 94.62,87.14 94.22,86.74 93.95,86.74 93.33,86.12 93.33,85.9 92.93,85.5 92.76,85.5 92.08,84.81 92.08,84.63 91.71,84.26 91.45,84.26 88.71,81.52 88.71,79.11 88.25,78.65 88.25,68.82 98.98,58.09 115.94,58.09 117.03,59.18 129.92,59.18 133.57,62.83 133.57,63.14 133.81,63.39 134.15,63.39 134.73,63.97 134.73,67.08 134.28,67.53 134.06,67.53 133.99,67.61 v1(133.99,68.05)
DI10-: length 81.3
  L05_SIG1 w0.076: v1(95.38,88.52) 94.94,88.52 94.86,88.44 94.86,87.04 94.32,86.5 94.05,86.5 93.57,86.02 93.57,85.8 93.03,85.26 92.86,85.26 92.32,84.71 92.32,84.53 91.81,84.02 91.55,84.02 88.95,81.42 88.95,81.12 89.06,81.01 89.07,81.01 89.18,80.9 89.18,80.74 89.07,80.63 89.06,80.63 88.95,80.52 88.95,79.01 88.49,78.55 88.49,68.92 88.68,68.73 88.93,68.73 89.08,68.58 89.08,68.34 99.08,58.33 100.5,58.33 100.71,58.55 100.88,58.55 101.1,58.33 115.84,58.33 116.07,58.56 116.07,58.79 116.29,59.02 116.52,59.02 116.93,59.42 129.82,59.42 130.09,59.69 130.09,59.98 130.21,60.1 130.5,60.1 133.32,62.93 133.32,63.24 133.71,63.63 134.05,63.63 134.49,64.07 134.49,64.54 134.26,64.77 134.26,64.92 134.49,65.15 134.49,65.81 134.26,66.04 134.26,66.19 134.49,66.42 134.49,66.98 134.18,67.29 134.06,67.29 133.99,67.21 v1(133.99,66.78)
DI11+: length 81.4
  L05_SIG1 w0.076: v1(92.84,87.25) 93.24,87.25 93.33,87.34 93.33,88.77 93.78,89.22 98.29,89.22 99.8,87.71 99.8,82.52 98.76,81.48 98.76,78.77 97.61,77.62 97.61,72.31 98.86,71.07 99.71,71.07 99.96,71.32 99.96,71.54 100.25,71.83 100.99,71.83 101.28,71.54 101.28,71.22 101.43,71.07 101.97,71.07 102.12,71.22 102.12,71.54 102.41,71.83 103.15,71.83 103.44,71.54 103.44,71.22 103.59,71.07 104.13,71.07 104.28,71.22 104.28,71.54 104.57,71.83 105.31,71.83 105.6,71.54 105.6,71.22 105.75,71.07 106.29,71.07 106.44,71.22 106.44,71.54 106.73,71.83 107.46,71.83 107.76,71.54 107.76,71.22 107.91,71.07 108.44,71.07 108.6,71.22 108.6,71.54 108.89,71.83 109.62,71.83 109.92,71.54 109.92,71.22 110.07,71.07 110.6,71.07 110.76,71.22 110.76,71.54 111.05,71.83 111.78,71.83 112.08,71.54 112.08,71.22 112.23,71.07 112.76,71.07 112.91,71.22 112.91,71.54 113.21,71.83 113.94,71.83 114.24,71.54 114.24,71.22 114.39,71.07 114.92,71.07 115.07,71.22 115.07,71.54 115.37,71.83 116.1,71.83 116.39,71.54 116.39,71.22 116.55,71.07 117.08,71.07 117.23,71.22 117.23,71.54 117.53,71.83 118.26,71.83 118.55,71.54 118.55,71.22 118.71,71.07 119.24,71.07 119.39,71.22 119.39,71.54 119.69,71.83 120.42,71.83 120.71,71.54 120.71,71.22 120.86,71.07 121.4,71.07 121.55,71.22 121.55,71.54 121.84,71.83 122.58,71.83 122.87,71.54 122.87,71.22 123.02,71.07 123.56,71.07 123.71,71.22 123.71,71.54 124,71.83 124.74,71.83 125.03,71.54 125.03,71.22 125.18,71.07 128.18,71.07 131.03,73.91 132.93,73.91 133.57,73.28 133.57,71.68 133.81,71.44 134.09,71.44 134.81,70.71 134.81,69 135.01,68.8 135.18,68.8 135.25,68.88 v1(135.25,69.32)
DI11-: length 81.3
  L05_SIG1 w0.076: v1(135.25,68.05) 135.25,68.48 135.18,68.56 134.91,68.56 134.57,68.9 134.57,70.61 133.99,71.2 133.71,71.2 133.32,71.58 133.32,73.18 132.83,73.67 131.13,73.67 128.28,70.83 125.08,70.83 124.79,71.12 124.79,71.44 124.64,71.59 124.1,71.59 123.95,71.44 123.95,71.12 123.66,70.83 122.92,70.83 122.63,71.12 122.63,71.44 122.48,71.59 121.94,71.59 121.79,71.44 121.79,71.12 121.5,70.83 120.76,70.83 120.47,71.12 120.47,71.44 120.32,71.59 119.79,71.59 119.63,71.44 119.63,71.12 119.34,70.83 118.61,70.83 118.31,71.12 118.31,71.44 118.16,71.59 117.63,71.59 117.47,71.44 117.47,71.12 117.18,70.83 116.45,70.83 116.15,71.12 116.15,71.44 116,71.59 115.47,71.59 115.31,71.44 115.31,71.12 115.02,70.83 114.29,70.83 113.99,71.12 113.99,71.44 113.84,71.59 113.31,71.59 113.16,71.44 113.16,71.12 112.86,70.83 112.13,70.83 111.83,71.12 111.83,71.44 111.68,71.59 111.15,71.59 111,71.44 111,71.12 110.7,70.83 109.97,70.83 109.68,71.12 109.68,71.44 109.52,71.59 108.99,71.59 108.84,71.44 108.84,71.12 108.54,70.83 107.81,70.83 107.52,71.12 107.52,71.44 107.36,71.59 106.83,71.59 106.68,71.44 106.68,71.12 106.39,70.83 105.65,70.83 105.36,71.12 105.36,71.44 105.21,71.59 104.67,71.59 104.52,71.44 104.52,71.12 104.23,70.83 103.49,70.83 103.2,71.12 103.2,71.44 103.05,71.59 102.51,71.59 102.36,71.44 102.36,71.12 102.07,70.83 101.33,70.83 101.04,71.12 101.04,71.44 100.89,71.59 100.35,71.59 100.2,71.44 100.2,71.22 99.81,70.83 98.76,70.83 97.37,72.21 97.37,77.72 98.51,78.87 98.51,81.58 99.56,82.62 99.56,86.53 99.42,86.67 99.42,86.91 99.56,87.05 99.56,87.61 98.77,88.39 98.55,88.39 98.39,88.55 98.39,88.77 98.19,88.98 96.46,88.98 96.33,88.85 96.03,88.85 95.9,88.98 93.88,88.98 93.57,88.67 93.57,87.38 93.71,87.25 v1(94.11,87.25)
DID0+: length 81.2
  L08_SIG2 w0.076: v1(139.06,97.26) 139.06,96.82 138.99,96.74 130.77,96.74 124.89,102.62 121.87,102.62 121.38,102.13 121.38,101.54 121.23,101.38 120.7,101.38 120.54,101.54 120.54,102.33 120.25,102.62 119.52,102.62 119.22,102.33 119.22,101.54 119.07,101.38 118.54,101.38 118.38,101.54 118.38,102.33 118.09,102.62 117.36,102.62 117.06,102.33 117.06,101.54 116.91,101.38 116.38,101.38 116.23,101.54 116.23,102.33 115.93,102.62 115.2,102.62 114.9,102.33 114.9,101.54 114.75,101.38 114.22,101.38 114.07,101.54 114.07,102.33 113.77,102.62 113.04,102.62 112.75,102.33 112.75,101.54 112.59,101.38 112.06,101.38 111.91,101.54 111.91,102.33 111.61,102.62 110.88,102.62 110.59,102.33 110.59,101.54 110.43,101.38 109.9,101.38 109.75,101.54 109.75,102.33 109.45,102.62 108.72,102.62 108.43,102.33 108.43,101.54 108.28,101.38 107.74,101.38 107.59,101.54 107.59,102.33 107.3,102.62 106.56,102.62 106.27,102.33 106.27,101.54 106.12,101.38 105.58,101.38 105.43,101.54 105.43,102.33 105.14,102.62 104.4,102.62 104.11,102.33 104.11,101.54 103.96,101.38 103.42,101.38 103.27,101.54 103.27,102.27 102.92,102.62 86.94,102.62 84.53,100.21 84.53,97.3 84.13,96.91 82.78,96.91 82.68,97.01 v1(82.68,97.41)
DID0-: length 81.2
  L08_SIG2 w0.076: v1(82.68,96.14) 82.68,96.54 82.78,96.64 84.25,96.64 84.71,97.1 84.71,97.14 84.77,97.2 84.77,100.11 87.04,102.38 102.82,102.38 103.03,102.17 103.03,101.44 103.32,101.14 104.06,101.14 104.35,101.44 104.35,102.23 104.5,102.38 105.04,102.38 105.19,102.23 105.19,101.44 105.48,101.14 106.22,101.14 106.51,101.44 106.51,102.23 106.66,102.38 107.2,102.38 107.35,102.23 107.35,101.44 107.64,101.14 108.38,101.14 108.67,101.44 108.67,102.23 108.82,102.38 109.35,102.38 109.51,102.23 109.51,101.44 109.8,101.14 110.53,101.14 110.83,101.44 110.83,102.23 110.98,102.38 111.51,102.38 111.67,102.23 111.67,101.44 111.96,101.14 112.69,101.14 112.99,101.44 112.99,102.23 113.14,102.38 113.67,102.38 113.83,102.23 113.83,101.44 114.12,101.14 114.85,101.14 115.15,101.44 115.15,102.23 115.3,102.38 115.83,102.38 115.98,102.23 115.98,101.44 116.28,101.14 117.01,101.14 117.31,101.44 117.31,102.23 117.46,102.38 117.99,102.38 118.14,102.23 118.14,101.44 118.44,101.14 119.17,101.14 119.46,101.44 119.46,102.23 119.62,102.38 120.15,102.38 120.3,102.23 120.3,101.44 120.6,101.14 121.33,101.14 121.62,101.44 121.62,102.03 121.97,102.38 124.79,102.38 130.67,96.5 138.99,96.5 139.06,96.42 v1(139.06,95.99)
DID1+: length 81.3
  L05_SIG1 w0.076: v1(133.99,98.53) 133.99,98.09 133.91,98.01 132.58,98.01 132.14,98.45 132.14,101.37 132.79,102.02 132.79,103.53 132.17,104.15 132.17,107.18 132.6,107.61 132.6,109.37 131.52,110.45 108.46,110.45 106.88,108.88 106.25,108.88 104.67,110.45 84.81,110.45 83.17,108.81 83.17,94.5 83.04,94.37 82.78,94.37 82.68,94.47 v1(82.68,94.87)
DID1-: length 81.3
  L05_SIG1 w0.076: v1(82.68,93.6) 82.68,94 82.78,94.1 83.15,94.1 83.41,94.36 83.41,108.71 84.91,110.21 104.57,110.21 106.15,108.64 106.98,108.64 108.56,110.21 131.42,110.21 132.36,109.27 132.36,107.71 131.93,107.28 131.93,104.05 132.55,103.43 132.55,102.12 131.9,101.47 131.9,98.35 132.48,97.77 133.91,97.77 133.99,97.69 v1(133.99,97.26)
DID2+: length 81.2
  L05_SIG1 w0.076: v1(83.95,96.14) 83.95,95.74 84.05,95.64 84.26,95.64 84.44,95.82 84.44,106.84 86.84,109.25 100.39,109.25 101.42,108.22 107.62,108.22 108.32,108.92 109.07,108.92 109.4,108.58 109.93,108.58 110.09,108.74 110.09,109.05 110.38,109.35 111.11,109.35 111.41,109.05 111.41,108.74 111.56,108.58 112.09,108.58 112.25,108.74 112.25,109.05 112.54,109.35 113.27,109.35 113.57,109.05 113.57,108.74 113.72,108.58 114.25,108.58 114.4,108.74 114.4,109.05 114.7,109.35 115.43,109.35 115.73,109.05 115.73,108.74 115.88,108.58 116.41,108.58 116.56,108.74 116.56,109.05 116.86,109.35 117.59,109.35 117.88,109.05 117.88,108.74 118.04,108.58 118.57,108.58 118.72,108.74 118.72,108.87 119.2,109.35 119.75,109.35 120.51,108.58 128.36,108.58 129.58,107.37 129.58,104.64 130.98,103.24 130.98,95.86 131.36,95.47 135.18,95.47 135.25,95.55 v1(135.25,95.99)
DID2-: length 81.2
  L05_SIG1 w0.076: v1(83.95,94.87) 83.95,95.27 84.05,95.37 84.33,95.37 84.68,95.72 84.68,106.74 86.94,109 100.29,109 101.32,107.98 107.72,107.98 108.42,108.67 108.97,108.67 109.3,108.34 110.03,108.34 110.33,108.64 110.33,108.95 110.48,109.11 111.01,109.11 111.17,108.95 111.17,108.64 111.46,108.34 112.19,108.34 112.49,108.64 112.49,108.95 112.64,109.11 113.17,109.11 113.33,108.95 113.33,108.64 113.62,108.34 114.35,108.34 114.65,108.64 114.65,108.95 114.8,109.11 115.33,109.11 115.48,108.95 115.48,108.64 115.78,108.34 116.51,108.34 116.81,108.64 116.81,108.95 116.96,109.11 117.49,109.11 117.64,108.95 117.64,108.64 117.94,108.34 118.67,108.34 118.96,108.64 118.96,108.77 119.3,109.11 119.65,109.11 120.41,108.34 128.26,108.34 129.34,107.27 129.34,104.54 130.73,103.14 130.73,95.76 131.26,95.23 135.18,95.23 135.25,95.15 v1(135.25,94.72)
DID3+: length 81.2
  L05_SIG1 w0.076: v1(85.22,97.41) 85.22,97.01 85.32,96.91 86.59,96.91 86.98,97.3 86.98,106.62 88.39,108.02 91.42,108.02 93.7,105.74 100.48,105.74 102.16,107.42 105.32,107.42 105.99,106.74 106.52,106.74 106.67,106.9 106.67,107.16 106.97,107.45 107.7,107.45 107.99,107.16 107.99,106.9 108.15,106.74 108.68,106.74 108.83,106.9 108.83,107.16 109.13,107.45 109.86,107.45 110.15,107.16 110.15,106.9 110.31,106.74 110.84,106.74 110.99,106.9 110.99,107.16 111.29,107.45 112.02,107.45 112.31,107.16 112.31,106.9 112.47,106.74 113,106.74 113.15,106.9 113.15,107.16 113.44,107.45 114.18,107.45 114.47,107.16 114.47,106.9 114.62,106.74 115.16,106.74 115.31,106.9 115.31,107.16 115.6,107.45 116.34,107.45 116.63,107.16 116.63,106.9 116.78,106.74 117.32,106.74 117.47,106.9 117.47,107.16 117.76,107.45 118.5,107.45 118.79,107.16 118.79,106.9 118.94,106.74 119.48,106.74 119.63,106.9 119.63,107.16 119.92,107.45 120.66,107.45 120.95,107.16 120.95,106.9 121.1,106.74 121.63,106.74 121.79,106.9 121.79,107.16 122.08,107.45 122.81,107.45 123.11,107.16 123.11,106.9 123.26,106.74 123.79,106.74 123.95,106.9 123.95,107.16 124.24,107.45 124.97,107.45 125.27,107.16 125.27,106.9 125.42,106.74 125.95,106.74 126.66,107.45 127.53,107.45 128.05,106.93 128.05,104.42 129.6,102.87 129.6,95.68 131.06,94.22 133.93,94.22 133.99,94.28 v1(133.99,94.72)
DID3-: length 81.3
  L05_SIG1 w0.076: v1(133.99,93.45) 133.99,93.88 133.89,93.98 130.96,93.98 129.36,95.58 129.36,102.77 127.81,104.32 127.81,106.83 127.43,107.21 126.76,107.21 126.05,106.5 125.32,106.5 125.03,106.8 125.03,107.06 124.87,107.21 124.34,107.21 124.19,107.06 124.19,106.8 123.89,106.5 123.16,106.5 122.87,106.8 122.87,107.06 122.71,107.21 122.18,107.21 122.03,107.06 122.03,106.8 121.73,106.5 121,106.5 120.71,106.8 120.71,107.06 120.56,107.21 120.02,107.21 119.87,107.06 119.87,106.8 119.58,106.5 118.84,106.5 118.55,106.8 118.55,107.06 118.4,107.21 117.86,107.21 117.71,107.06 117.71,106.8 117.42,106.5 116.68,106.5 116.39,106.8 116.39,107.06 116.24,107.21 115.7,107.21 115.55,107.06 115.55,106.8 115.26,106.5 114.52,106.5 114.23,106.8 114.23,107.06 114.08,107.21 113.54,107.21 113.39,107.06 113.39,106.8 113.1,106.5 112.37,106.5 112.07,106.8 112.07,107.06 111.92,107.21 111.39,107.21 111.23,107.06 111.23,106.8 110.94,106.5 110.21,106.5 109.91,106.8 109.91,107.06 109.76,107.21 109.23,107.21 109.07,107.06 109.07,106.8 108.78,106.5 108.05,106.5 107.75,106.8 107.75,107.06 107.6,107.21 107.07,107.21 106.92,107.06 106.92,106.8 106.62,106.5 105.89,106.5 105.21,107.18 102.26,107.18 100.58,105.5 93.6,105.5 91.32,107.78 88.49,107.78 87.22,106.52 87.22,97.17 86.7,96.64 85.32,96.64 85.22,96.54 v1(85.22,96.14)
DID4+: length 81.3
  L08_SIG2 w0.076: v1(85.22,94.87) 85.22,94.49 85.33,94.37 85.56,94.37 85.8,94.61 85.8,99.4 87.73,101.33 99.73,101.33 102.13,98.93 104.18,98.93 104.33,99.09 104.33,99.83 104.62,100.13 105.36,100.13 105.65,99.83 105.65,99.09 105.8,98.93 106.34,98.93 106.49,99.09 106.49,99.83 106.78,100.13 107.52,100.13 107.81,99.83 107.81,99.09 107.96,98.93 108.5,98.93 108.65,99.09 108.65,99.83 108.94,100.13 109.68,100.13 109.97,99.83 109.97,99.09 110.12,98.93 110.66,98.93 110.81,99.09 110.81,99.83 111.1,100.13 111.84,100.13 112.13,99.83 112.13,99.09 112.28,98.93 112.81,98.93 112.97,99.09 112.97,99.83 113.26,100.13 113.99,100.13 114.29,99.83 114.29,99.09 114.44,98.93 114.97,98.93 115.13,99.09 115.13,99.83 115.42,100.13 116.15,100.13 116.45,99.83 116.45,99.09 116.6,98.93 117.13,98.93 117.29,99.09 117.29,99.83 117.58,100.13 118.31,100.13 118.61,99.83 118.61,99.09 118.76,98.93 119.29,98.93 119.44,99.09 119.44,99.83 119.74,100.13 120.47,100.13 120.77,99.83 120.77,99.09 120.92,98.93 121.45,98.93 121.6,99.09 121.6,99.83 121.9,100.13 122.63,100.13 123.82,98.93 126.72,98.93 130.2,95.46 136.78,95.46 137.29,94.95 137.29,93.25 137.61,92.93 138.99,92.93 139.06,93.01 v1(139.06,93.45)
